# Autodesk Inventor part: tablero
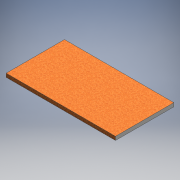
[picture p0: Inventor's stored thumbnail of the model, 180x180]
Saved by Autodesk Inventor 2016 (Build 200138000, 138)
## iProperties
Created: 2016-06
Part Number: tablero
Material: Generic
Document SubType Name: Modeling
Designer: yesi alvarez
Mass: 32000 g
Surface Area: 14400 cm^2
Volume: 32000 cm^3
Density: 1 g/cm^3
Appearance: Default
Author: yesi alvarez
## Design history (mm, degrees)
sketch "Sketch1"
  geometry: L1 (0, 0)-(1500, 0); L2 (1500, 0)-(1500, 800); L3 (1500, 800)-(0, 800); L4 (0, 800)-(0, 0)
  constraints: 8 end point, 2 parallel, 1 horizontal, 1 perpendicular
  dimensions: "d0" = 1500 distance of L3.end L2.end; "d1" = 800 distance of L2.end L1.end
extrude "Extrusion1" new body sketch "Sketch1" distance "d2" = 50; taper "d3" = 0 deg
body "Solid1"
